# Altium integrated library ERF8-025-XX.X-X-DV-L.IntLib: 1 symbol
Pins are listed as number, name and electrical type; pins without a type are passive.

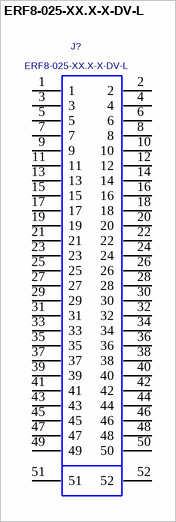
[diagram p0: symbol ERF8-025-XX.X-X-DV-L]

## ERF8-025-XX.X-X-DV-L
designator J?
0.8mm Edge Rate Socket Assembly, Double Vertical Row, 50 Pins.; MANUFACTURER: SAMTEC
footprint ERF8-025-XX.X-X-DV-L
pins: 1, 2, 3, 4, 5, 6, 7, 8, 9, 10, 11, 12, 13, 14, 15, 16, 17, 18, 19, 20, 21, 22, 23, 24, 25, 26, 27, 28, 29, 30, 31, 32, 33, 34, 35, 36, 37, 38, 39, 40, 41, 42, 43, 44, 45, 46, 47, 48, 49, 50, 51, 52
